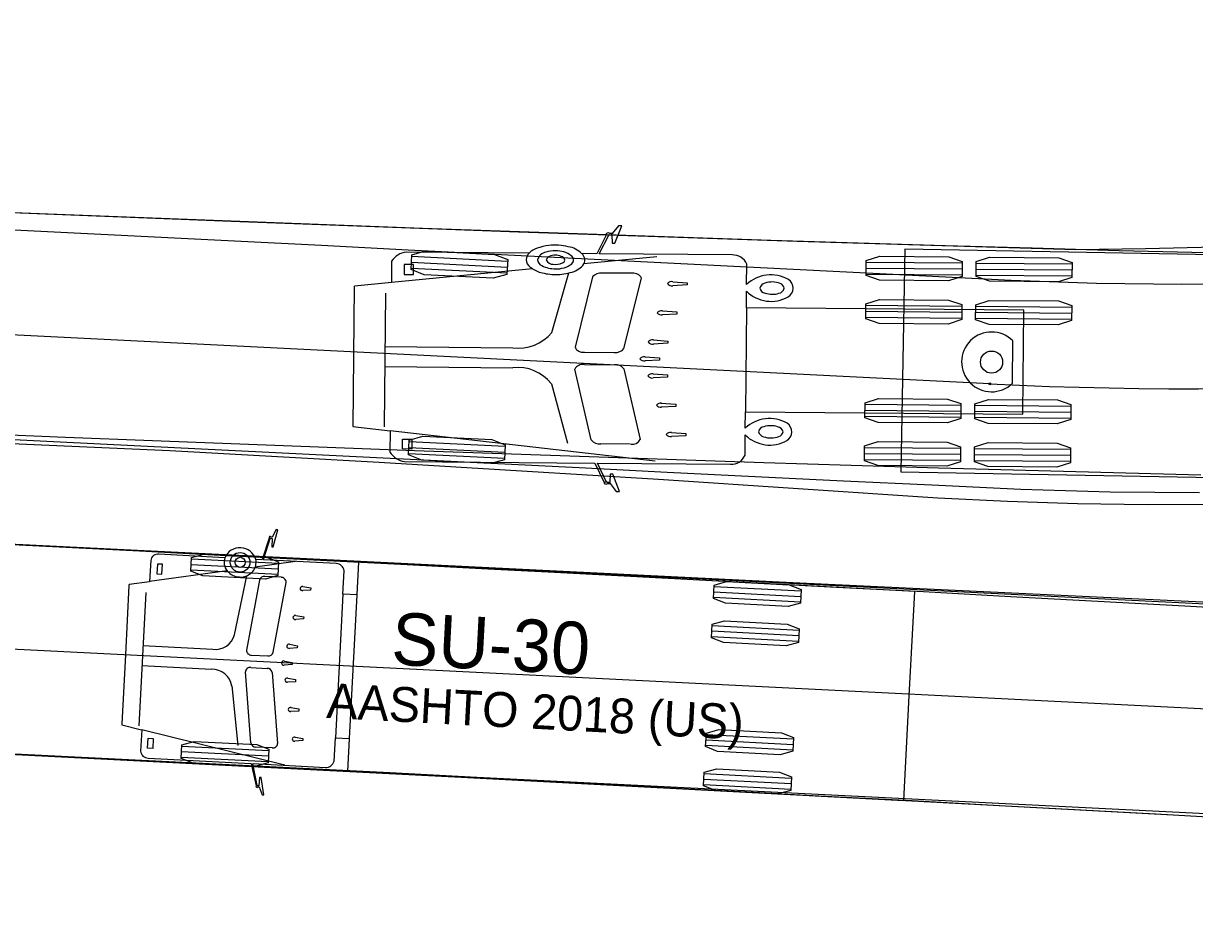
# Model space of a CAD drawing. Extents: x 260275 to 261282, y 610916 to 614143.
# Drawn here: x 260913.77 to 260958.53, y 612581.07 to 612614.79 of the extents above; entities that cross this region are included whole.
import ezdxf

# ---------------------------------------------------------------- set-up
doc = ezdxf.new("R2010")
doc.units = 0
doc.layers.add('TopoDOT_Transients', color=7, linetype='Continuous')

msp = doc.modelspace()

# ---------------------------------------------------------------- linework, layer by layer
at = {"layer": 'TopoDOT_Transients'}
for p, q in [((260950.706, 612601.011), (260777.483, 612609.681)), ((260936.261, 612606.737), (260936.278, 612606.757)), ((260936.262, 612606.711), (260936.261, 612606.737)), ((260933.106, 612606.005), (260928.405, 612606.046)), ((260928.323, 612605.571), (260928.32, 612605.192)), ((260928.679, 612605.568), (260928.323, 612605.571)), ((260928.605, 612605.661), (260932.267, 612605.477)), ((260928.616, 612605.89), (260932.278, 612605.706)), ((260928.676, 612605.189), (260928.679, 612605.568)), ((260937.981, 612605.862), (260935.19, 612605.593)), ((260941.411, 612604.807), (260941.417, 612605.582)), ((260945.985, 612605.663), (260949.651, 612605.631)), ((260950.185, 612605.626), (260953.851, 612605.594)), ((260933.234, 612605.405), (260927.837, 612604.886)), ((260928.32, 612605.192), (260928.676, 612605.189)), ((260928.593, 612605.432), (260932.255, 612605.248)), ((260933.967, 612602.978), (260934.623, 612605.249)), ((260935.522, 612605.097), (260934.854, 612602.409)), ((260937.024, 612605.236), (260935.893, 612605.246)), ((260945.981, 612605.205), (260949.647, 612605.173)), ((260945.983, 612605.434), (260949.649, 612605.402)), ((260950.181, 612605.168), (260953.847, 612605.136)), ((260950.183, 612605.397), (260953.849, 612605.365)), ((260926.409, 612604.748), (260926.363, 612599.378)), ((260936.725, 612602.362), (260937.393, 612605.051)), ((260939.137, 612604.793), (260938.587, 612604.762)), ((260938.588, 612604.916), (260939.138, 612604.876)), ((260939.138, 612604.876), (260939.137, 612604.793)), ((260927.608, 612604.472), (260927.564, 612599.367)), ((260938.193, 612603.803), (260938.742, 612603.762)), ((260938.742, 612603.762), (260938.742, 612603.679)), ((260941.403, 612603.919), (260941.368, 612599.945)), ((260945.968, 612603.784), (260949.635, 612603.752)), ((260945.97, 612604.013), (260949.637, 612603.981)), ((260950.168, 612603.747), (260953.835, 612603.715)), ((260950.17, 612603.976), (260953.837, 612603.944)), ((260938.742, 612603.679), (260938.192, 612603.648)), ((260945.966, 612603.555), (260949.633, 612603.523)), ((260950.166, 612603.518), (260953.833, 612603.486)), ((260927.591, 612602.435), (260932.482, 612602.393)), ((260938.398, 612602.565), (260937.848, 612602.534)), ((260937.849, 612602.688), (260938.398, 612602.648)), ((260938.398, 612602.648), (260938.398, 612602.565)), ((260951.574, 612601.035), (260951.588, 612602.651)), ((260935.222, 612602.224), (260936.353, 612602.214)), ((260937.535, 612602.043), (260938.084, 612602.002)), ((260938.084, 612602.002), (260938.083, 612601.92)), ((260927.584, 612601.67), (260932.475, 612601.627)), ((260935.467, 612598.87), (260934.846, 612601.57)), ((260935.218, 612601.748), (260936.349, 612601.738)), ((260936.718, 612601.583), (260937.339, 612598.884)), ((260938.083, 612601.92), (260937.534, 612601.889)), ((260938.386, 612601.269), (260937.836, 612601.238)), ((260937.838, 612601.392), (260938.387, 612601.351)), ((260938.387, 612601.351), (260938.386, 612601.269)), ((260933.949, 612601.016), (260934.563, 612598.746)), ((260938.711, 612600.149), (260938.136, 612600.117)), ((260938.137, 612600.271), (260938.712, 612600.231)), ((260938.712, 612600.231), (260938.711, 612600.149)), ((260945.937, 612600.23), (260949.604, 612600.198)), ((260950.137, 612600.193), (260953.804, 612600.161)), ((260945.933, 612599.771), (260949.6, 612599.739)), ((260945.935, 612600.001), (260949.602, 612599.969)), ((260950.133, 612599.735), (260953.8, 612599.703)), ((260950.135, 612599.964), (260953.802, 612599.932)), ((260937.913, 612598.062), (260927.788, 612599.215)), ((260928.261, 612598.522), (260928.265, 612598.901)), ((260928.265, 612598.901), (260928.621, 612598.898)), ((260928.516, 612598.807), (260932.179, 612598.625)), ((260928.621, 612598.898), (260928.617, 612598.519)), ((260939.087, 612599.028), (260938.537, 612598.997)), ((260938.538, 612599.151), (260939.087, 612599.111)), ((260939.087, 612599.111), (260939.087, 612599.028)), ((260941.354, 612598.282), (260941.36, 612599.058)), ((260928.617, 612598.519), (260928.261, 612598.522)), ((260928.505, 612598.578), (260932.167, 612598.396)), ((260936.967, 612598.705), (260935.836, 612598.715)), ((260945.923, 612598.58), (260949.59, 612598.548)), ((260950.123, 612598.543), (260953.789, 612598.511)), ((260928.494, 612598.349), (260932.156, 612598.167)), ((260945.919, 612598.122), (260949.586, 612598.09)), ((260945.921, 612598.351), (260949.588, 612598.319)), ((260950.119, 612598.085), (260953.785, 612598.053)), ((260950.121, 612598.314), (260953.787, 612598.282)), ((261025.504, 612585.252), (260776.884, 612597.696)), ((260936.18, 612597.243), (260936.178, 612597.217)), ((260936.178, 612597.217), (260936.195, 612597.197)), ((260921.472, 612594.365), (260918.953, 612594.498)), ((260918.892, 612594.125), (260918.872, 612593.747)), ((260919.085, 612594.115), (260918.892, 612594.125)), ((260919.066, 612593.737), (260919.085, 612594.115)), ((260920.175, 612593.903), (260923.504, 612593.737)), ((260920.185, 612594.111), (260923.514, 612593.945)), ((260920.196, 612594.32), (260923.525, 612594.153)), ((260924.17, 612594.223), (260922.636, 612594.01)), ((260921.561, 612593.862), (260918.594, 612593.451)), ((260918.872, 612593.747), (260919.066, 612593.737)), ((260921.844, 612591.423), (260922.31, 612593.677)), ((260922.793, 612593.508), (260922.3, 612590.836)), ((260923.619, 612593.617), (260923.003, 612593.649)), ((260918.449, 612593.042), (260918.181, 612587.944)), ((260923.318, 612590.752), (260923.811, 612593.425)), ((260924.75, 612593.132), (260924.448, 612593.112)), ((260924.456, 612593.266), (260924.754, 612593.215)), ((260924.754, 612593.215), (260924.75, 612593.132)), ((260940.159, 612593.064), (260943.487, 612592.888)), ((260940.17, 612593.272), (260943.498, 612593.096)), ((260925.983, 612592.972), (260925.694, 612587.488)), ((260926.514, 612592.944), (260926.225, 612587.46)), ((260940.148, 612592.856), (260943.477, 612592.68)), ((260924.188, 612592.162), (260924.485, 612592.11)), ((260924.485, 612592.11), (260924.481, 612592.028)), ((260924.481, 612592.028), (260924.179, 612592.008)), ((260940.091, 612591.774), (260943.42, 612591.599)), ((260940.069, 612591.358), (260943.398, 612591.182)), ((260940.08, 612591.566), (260943.409, 612591.391)), ((260918.342, 612591.008), (260921.007, 612590.868)), ((260924.24, 612590.922), (260923.939, 612590.902)), ((260923.947, 612591.056), (260924.244, 612591.004)), ((260924.244, 612591.004), (260924.24, 612590.922)), ((260922.493, 612590.644), (260923.108, 612590.612)), ((260923.745, 612590.417), (260924.042, 612590.366)), ((260924.042, 612590.366), (260924.038, 612590.283)), ((260918.302, 612590.243), (260920.967, 612590.103)), ((260922.466, 612587.289), (260922.256, 612589.998)), ((260922.468, 612590.169), (260923.083, 612590.137)), ((260923.277, 612589.975), (260923.487, 612587.266)), ((260924.038, 612590.283), (260923.736, 612590.263)), ((260921.741, 612589.463), (260921.967, 612587.184)), ((260924.172, 612589.627), (260923.87, 612589.607)), ((260923.879, 612589.761), (260924.176, 612589.709)), ((260924.176, 612589.709), (260924.172, 612589.627)), ((260923.988, 612588.636), (260924.299, 612588.584)), ((260924.299, 612588.584), (260924.295, 612588.502)), ((260924.295, 612588.502), (260923.98, 612588.482)), ((260923.76, 612586.434), (260918.296, 612587.788)), ((260939.872, 612587.613), (260943.2, 612587.438)), ((260918.521, 612587.086), (260918.541, 612587.464)), ((260918.541, 612587.464), (260918.735, 612587.454)), ((260918.735, 612587.454), (260918.715, 612587.076)), ((260919.821, 612587.163), (260923.15, 612586.996)), ((260924.446, 612587.375), (260924.145, 612587.355)), ((260924.153, 612587.509), (260924.451, 612587.458)), ((260924.451, 612587.458), (260924.446, 612587.375)), ((260939.85, 612587.197), (260943.178, 612587.022)), ((260939.861, 612587.405), (260943.189, 612587.23)), ((260918.715, 612587.076), (260918.521, 612587.086)), ((260919.8, 612586.747), (260923.129, 612586.58)), ((260919.81, 612586.955), (260923.14, 612586.788)), ((260923.275, 612587.095), (260922.659, 612587.127)), ((260939.782, 612585.907), (260943.111, 612585.732)), ((260939.793, 612586.115), (260943.121, 612585.94)), ((260939.771, 612585.699), (260943.1, 612585.524))]:
    msp.add_line(p, q, dxfattribs=at)
for points in [[(260911.385, 612607.632), (260922.039, 612607.21), (260932.691, 612606.819), (260943.342, 612606.462), (260953.993, 612606.15), (260956.658, 612606.184), (260959.324, 612606.244), (260961.99, 612606.332), (260964.656, 612606.454), (260967.323, 612606.613), (260969.991, 612606.814), (260972.66, 612607.058), (260975.329, 612607.346), (260977.999, 612607.674), (260980.67, 612608.042), (260983.343, 612608.449), (260986.018, 612608.892), (260988.694, 612609.369), (260991.374, 612609.879), (260994.059, 612610.418), (260996.748, 612610.983), (261002.487, 612612.256), (261003.848, 612612.757)], [(260958.984, 612606.013), (260955.656, 612606.101), (260952.328, 612606.193), (260949, 612606.289), (260945.672, 612606.389), (260942.344, 612606.494), (260939.016, 612606.602), (260935.687, 612606.715), (260932.359, 612606.83), (260929.03, 612606.95), (260925.701, 612607.072), (260922.372, 612607.198), (260919.043, 612607.326), (260915.714, 612607.457), (260912.384, 612607.591)], [(260961.3, 612604.839), (260958.04, 612604.805), (260954.781, 612604.844), (260951.526, 612604.955), (260948.258, 612605.122), (260944.976, 612605.291), (260941.686, 612605.459), (260938.39, 612605.627), (260935.089, 612605.794), (260931.782, 612605.96), (260928.472, 612606.127), (260925.159, 612606.293), (260921.843, 612606.46), (260918.524, 612606.626), (260915.204, 612606.792), (260911.882, 612606.959)], [(260936.18, 612606.711), (260936.262, 612606.711), (260936.275, 612606.391), (260936.378, 612606.39), (260936.642, 612607.049), (260936.522, 612607.05), (260936.278, 612606.757), (260936.191, 612606.757)], [(260936.057, 612606.718), (260935.682, 612605.982), (260935.108, 612605.987)], [(260940.863, 612605.937), (260935.781, 612605.981), (260936.143, 612606.7), (260936.144, 612606.7)], [(260995.384, 612605.258), (260995.384, 612605.281), (260947.463, 612606.153), (260947.386, 612601.903), (260947.308, 612597.654), (260995.23, 612596.782), (260995.23, 612596.804)], [(260927.844, 612605.7), (260927.837, 612604.886), (260926.421, 612604.749)], [(260926.409, 612604.748), (260926.363, 612599.378), (260927.788, 612599.215), (260927.781, 612598.401)], [(260941.363, 612599.315), (260941.368, 612599.945), (260951.968, 612599.853), (260952.002, 612603.826), (260941.403, 612603.919), (260941.408, 612604.549)], [(261003.728, 612596.585), (260998.439, 612596.713), (260972.791, 612597.178), (260970.113, 612596.922), (260967.436, 612596.717), (260964.759, 612596.562), (260962.082, 612596.455), (260959.407, 612596.397), (260956.732, 612596.387), (260954.059, 612596.425), (260951.386, 612596.511), (260948.716, 612596.644), (260938.041, 612597.354), (260927.368, 612598.004), (260919.365, 612598.455), (260908.692, 612598.918)], [(260958.718, 612596.842), (260955.304, 612596.87), (260951.89, 612596.973), (260948.494, 612597.133), (260945.113, 612597.298), (260941.739, 612597.463), (260938.372, 612597.629), (260935.011, 612597.796), (260931.655, 612597.963), (260928.302, 612598.13), (260924.953, 612598.297), (260921.607, 612598.464), (260918.263, 612598.631), (260914.921, 612598.798), (260911.58, 612598.965)], [(260958.767, 612597.516), (260955.428, 612597.604), (260952.089, 612597.696), (260948.75, 612597.793), (260945.411, 612597.893), (260942.073, 612597.998), (260938.734, 612598.107), (260935.396, 612598.22), (260932.059, 612598.336), (260928.722, 612598.455), (260925.385, 612598.578), (260922.048, 612598.704), (260918.712, 612598.833), (260915.376, 612598.964), (260912.04, 612599.098)], [(260928.335, 612598.046), (260935.612, 612597.982), (260935.974, 612597.24)], [(260936.061, 612597.256), (260936.061, 612597.256), (260935.711, 612597.981), (260940.793, 612597.937)], [(260936.107, 612597.198), (260936.195, 612597.197), (260936.433, 612596.9), (260936.553, 612596.899), (260936.301, 612597.563), (260936.198, 612597.563), (260936.18, 612597.243), (260936.098, 612597.245)], [(260900.569, 612595.515), (260943.182, 612593.414), (260964.509, 612592.414), (260975.188, 612591.95), (260985.89, 612591.53), (260991.256, 612591.343), (260996.637, 612591.176), (261002.039, 612591.033), (261007.472, 612590.914)], [(260923.23, 612595.107), (260923.274, 612595.106), (260923.274, 612595.105), (260923.266, 612594.788), (260923.266, 612594.785), (260923.322, 612594.782), (260923.323, 612594.785), (260923.497, 612595.433), (260923.497, 612595.436), (260923.432, 612595.439), (260923.285, 612595.151), (260923.285, 612595.151), (260923.237, 612595.153)], [(260961.528, 612592.459), (260958.19, 612592.626), (260954.854, 612592.793), (260951.52, 612592.96), (260948.186, 612593.127), (260944.853, 612593.294), (260941.521, 612593.461), (260938.189, 612593.627), (260934.858, 612593.794), (260931.528, 612593.961), (260928.197, 612594.128), (260924.867, 612594.294), (260921.538, 612594.461), (260918.208, 612594.628), (260914.879, 612594.794), (260911.55, 612594.961)], [(260961.494, 612592.322), (260958.163, 612592.51), (260954.832, 612592.695), (260951.502, 612592.877), (260948.172, 612593.056), (260944.842, 612593.234), (260941.512, 612593.41), (260938.183, 612593.584), (260934.853, 612593.757), (260931.524, 612593.93), (260928.195, 612594.101), (260924.867, 612594.272), (260921.538, 612594.442), (260918.209, 612594.611), (260914.881, 612594.78), (260911.552, 612594.949)], [(260923.162, 612595.116), (260923.162, 612595.116), (260922.893, 612594.297), (260922.88, 612594.291), (260922.653, 612594.303)], [(260925.729, 612594.141), (260922.958, 612594.287), (260922.946, 612594.292), (260923.209, 612595.097), (260923.209, 612595.097)], [(260918.637, 612594.261), (260918.594, 612593.454), (260918.589, 612593.45), (260917.811, 612593.342), (260917.807, 612593.3), (260917.668, 612590.66), (260917.529, 612588.02), (260917.529, 612587.978), (260918.291, 612587.789), (260918.296, 612587.784), (260918.253, 612586.978)], [(260925.647, 612586.59), (260925.694, 612587.484), (260925.698, 612587.487), (260926.224, 612587.46), (260926.224, 612587.449), (260926.159, 612586.207), (260947.416, 612585.088), (260947.626, 612589.082), (260947.837, 612593.077), (260926.58, 612594.196), (260926.514, 612592.955), (260926.513, 612592.944), (260925.987, 612592.972), (260925.983, 612592.975), (260926.03, 612593.87)], [(261004.659, 612581.071), (260999.422, 612581.614), (260994.161, 612582.095), (260988.884, 612582.526), (260983.594, 612582.919), (260978.296, 612583.283), (260967.681, 612583.949), (260957.051, 612584.56), (260935.769, 612585.699), (260893.177, 612587.866)], [(260961.01, 612584.476), (260957.69, 612584.642), (260954.37, 612584.808), (260951.048, 612584.974), (260947.725, 612585.14), (260944.401, 612585.307), (260941.077, 612585.473), (260937.752, 612585.639), (260934.427, 612585.806), (260931.101, 612585.972), (260927.775, 612586.139), (260924.448, 612586.305), (260921.121, 612586.472), (260917.794, 612586.638), (260914.467, 612586.805), (260911.14, 612586.971)], [(260961.039, 612584.335), (260957.716, 612584.523), (260954.392, 612584.707), (260951.068, 612584.888), (260947.743, 612585.068), (260944.418, 612585.245), (260941.092, 612585.421), (260937.765, 612585.595), (260934.439, 612585.768), (260931.112, 612585.94), (260927.785, 612586.112), (260924.458, 612586.282), (260921.13, 612586.452), (260917.803, 612586.622), (260914.475, 612586.791), (260911.147, 612586.959)], [(260918.542, 612586.709), (260922.47, 612586.502), (260922.482, 612586.494), (260922.664, 612585.652), (260922.664, 612585.651)], [(260922.712, 612585.666), (260922.712, 612585.666), (260922.536, 612586.494), (260922.548, 612586.498), (260925.318, 612586.352)], [(260922.735, 612585.607), (260922.782, 612585.604), (260922.782, 612585.604), (260922.898, 612585.302), (260922.963, 612585.299), (260922.963, 612585.301), (260922.858, 612585.964), (260922.857, 612585.967), (260922.802, 612585.97), (260922.801, 612585.967), (260922.776, 612585.651), (260922.776, 612585.65), (260922.732, 612585.653)]]:
    msp.add_lwpolyline(points, dxfattribs=at)
for points in [[(260928.59, 612605.376), (260928.619, 612605.947), (260929.141, 612606.093), (260931.777, 612605.961), (260932.281, 612605.763), (260932.252, 612605.191), (260931.731, 612605.045), (260929.094, 612605.178)], [(260945.98, 612605.148), (260945.985, 612605.72), (260946.5, 612605.888), (260949.14, 612605.865), (260949.652, 612605.688), (260949.647, 612605.116), (260949.132, 612604.948), (260946.492, 612604.971)], [(260950.18, 612605.111), (260950.185, 612605.683), (260950.7, 612605.851), (260953.34, 612605.828), (260953.852, 612605.651), (260953.847, 612605.079), (260953.332, 612604.911), (260950.692, 612604.934)], [(260945.966, 612603.498), (260945.971, 612604.07), (260946.486, 612604.238), (260949.126, 612604.215), (260949.637, 612604.038), (260949.632, 612603.466), (260949.118, 612603.298), (260946.478, 612603.321)], [(260950.166, 612603.461), (260950.171, 612604.033), (260950.686, 612604.201), (260953.326, 612604.178), (260953.837, 612604.001), (260953.832, 612603.429), (260953.318, 612603.261), (260950.678, 612603.284)], [(260945.933, 612599.715), (260945.938, 612600.287), (260946.453, 612600.454), (260949.093, 612600.431), (260949.604, 612600.255), (260949.599, 612599.683), (260949.085, 612599.515), (260946.445, 612599.538)], [(260950.133, 612599.678), (260950.138, 612600.25), (260950.653, 612600.418), (260953.292, 612600.395), (260953.804, 612600.218), (260953.799, 612599.646), (260953.284, 612599.478), (260950.645, 612599.501)], [(260928.491, 612598.293), (260928.519, 612598.864), (260929.041, 612599.011), (260931.677, 612598.879), (260932.181, 612598.682), (260932.153, 612598.11), (260931.632, 612597.964), (260928.995, 612598.095)], [(260945.919, 612598.065), (260945.924, 612598.637), (260946.438, 612598.805), (260949.078, 612598.781), (260949.59, 612598.605), (260949.585, 612598.033), (260949.07, 612597.865), (260946.43, 612597.888)], [(260950.118, 612598.028), (260950.123, 612598.6), (260950.638, 612598.768), (260953.278, 612598.745), (260953.79, 612598.568), (260953.785, 612597.996), (260953.27, 612597.828), (260950.63, 612597.851)], [(260920.172, 612593.852), (260920.198, 612594.371), (260920.672, 612594.504), (260923.069, 612594.384), (260923.527, 612594.205), (260923.501, 612593.685), (260923.027, 612593.552), (260920.63, 612593.672)], [(260940.145, 612592.804), (260940.172, 612593.323), (260940.647, 612593.455), (260943.043, 612593.329), (260943.501, 612593.148), (260943.474, 612592.629), (260943, 612592.497), (260940.603, 612592.623)], [(260940.066, 612591.306), (260940.094, 612591.825), (260940.568, 612591.957), (260942.964, 612591.831), (260943.422, 612591.65), (260943.395, 612591.131), (260942.921, 612590.999), (260940.524, 612591.125)], [(260939.847, 612587.145), (260939.874, 612587.665), (260940.349, 612587.796), (260942.745, 612587.67), (260943.203, 612587.489), (260943.176, 612586.97), (260942.701, 612586.838), (260940.305, 612586.964)], [(260919.797, 612586.695), (260919.823, 612587.214), (260920.297, 612587.347), (260922.694, 612587.227), (260923.153, 612587.048), (260923.127, 612586.528), (260922.653, 612586.395), (260920.256, 612586.515)], [(260939.768, 612585.647), (260939.795, 612586.167), (260940.27, 612586.299), (260942.666, 612586.172), (260943.124, 612585.991), (260943.097, 612585.472), (260942.623, 612585.34), (260940.226, 612585.466)]]:
    msp.add_lwpolyline(points, close=True, dxfattribs=at)
for centre, radius in [((260950.773, 612601.842), 0.424), ((260950.706, 612601.011), 0.0417), ((260950.706, 612601.011), 0.0417), ((260922.054, 612594.189), 0.374), ((260922.054, 612594.189), 0.193)]:
    msp.add_circle(centre, radius, dxfattribs=at)
for centre, radius, start, end in [((260958.205, 612750.824), 150, 267.13462, 294.9182), ((260936.07, 612606.739), 0.0244, 125.3178, 238.6321), ((260936.122, 612606.65), 0.127, 57.3952, 121.6043), ((260936.131, 612606.81), 0.11, 276.4439, 296.5522), ((260928.502, 612605.26), 0.792, 97.0332, 146.1886), ((260933.315, 612605.752), 0.328, 129.5881, 178.4924), ((260933.625, 612605.508), 0.719, 108.0301, 136.2871), ((260934.025, 612604.576), 1.731, 95.8848, 111.0826), ((260933.814, 612605.641), 0.407, 100.7304, 163.5348), ((260934.093, 612604.859), 1.234, 89.1294, 106.7116), ((260934.091, 612604.108), 2.204, 76.6988, 96.334), ((260934.161, 612605.182), 0.913, 52.8094, 93.0696), ((260934.448, 612605.341), 0.924, 44.3968, 80.675), ((260934.93, 612605.745), 0.301, 329.731, 53.6293), ((260933.366, 612605.779), 0.38, 182.8301, 233.3536), ((260933.69, 612605.778), 0.268, 184.5724, 248.25), ((260934.093, 612606.506), 1.098, 242.7655, 270.6581), ((260933.965, 612605.687), 0.22, 100.5096, 162.2079), ((260934.008, 612605.849), 0.27, 200.6487, 273.3925), ((260934.1, 612605.296), 0.631, 63.308, 106.1085), ((260934.112, 612606.19), 0.617, 261.7873, 294.9781), ((260934.164, 612606.32), 0.914, 266.3342, 308.3921), ((260934.342, 612605.747), 0.12, 284.4758, 69.9539), ((260934.596, 612605.748), 0.199, 313.303, 53.9423), ((260934.539, 612606.056), 0.799, 285.2992, 324.5668), ((260940.888, 612605.366), 0.571, 22.1928, 92.5843), ((260933.816, 612606.308), 1.074, 230.9563, 255.2252), ((260934.111, 612607.239), 2.049, 253.8808, 269.8061), ((260934.134, 612607.201), 2.012, 269.1411, 287.824), ((260935.837, 612604.846), 0.403, 82.0421, 141.5), ((260937.092, 612604.906), 0.334, 25.7646, 98.3626), ((260942.335, 612603.831), 1.344, 59.9095, 133.4643), ((260938.545, 612604.729), 0.192, 76.9495, 144.424), ((260938.547, 612604.95), 0.192, 214.5481, 282.0773), ((260942.19, 612604.583), 0.29, 105.6954, 161.8555), ((260942.157, 612604.722), 0.247, 191.217, 261.0961), ((260942.376, 612604.045), 0.86, 67.9644, 107.9338), ((260942.6, 612604.73), 0.262, 279.1826, 345.7078), ((260942.629, 612604.625), 0.228, 10.3026, 72.1974), ((260942.811, 612604.666), 0.383, 299.9705, 59.029), ((260942.349, 612605.508), 1.344, 225.5352, 299.09), ((260942.39, 612605.314), 0.879, 252.0366, 286.6318), ((260938.15, 612603.615), 0.192, 76.9495, 144.424), ((260938.152, 612603.836), 0.192, 214.5481, 282.0773), ((260932.702, 612604.009), 1.631, 262.2332, 320.8239), ((260950.773, 612601.85), 1.143, 44.4997, 314.4997), ((260935.156, 612602.562), 0.342, 207.9714, 277.8979), ((260937.806, 612602.501), 0.192, 76.9495, 144.424), ((260937.808, 612602.722), 0.192, 214.5481, 282.0773), ((260936.413, 612602.608), 0.397, 263.5756, 321.7386), ((260937.491, 612601.856), 0.192, 76.9495, 144.424), ((260937.493, 612602.077), 0.192, 214.5754, 282.05), ((260932.667, 612600.008), 1.631, 38.1756, 96.7663), ((260935.145, 612601.411), 0.342, 81.1015, 151.028), ((260936.402, 612601.343), 0.397, 37.2609, 95.4239), ((260937.794, 612601.205), 0.192, 76.9221, 144.4514), ((260937.796, 612601.426), 0.192, 214.5754, 282.05), ((260938.119, 612600.085), 0.192, 76.9221, 144.4514), ((260938.121, 612600.306), 0.192, 214.5754, 282.05), ((260942.287, 612598.34), 1.344, 59.9095, 133.4643), ((260942.108, 612599.13), 0.247, 97.9033, 167.7824), ((260942.331, 612598.533), 0.879, 72.3676, 106.9629), ((260942.551, 612599.113), 0.262, 13.2917, 79.8169), ((260942.755, 612599.174), 0.387, 300.9953, 58.0042), ((260935.787, 612599.115), 0.403, 217.4994, 276.9574), ((260937.041, 612599.034), 0.334, 260.6369, 333.2349), ((260938.495, 612598.964), 0.192, 76.9221, 144.4514), ((260938.497, 612599.185), 0.192, 214.5754, 282.05), ((260942.301, 612600.016), 1.344, 225.5352, 299.09), ((260942.144, 612599.267), 0.29, 197.144, 253.304), ((260942.339, 612599.803), 0.86, 251.0657, 291.0351), ((260942.582, 612599.218), 0.228, 286.802, 348.6969), ((260928.446, 612598.83), 0.792, 212.8108, 261.9663), ((260940.829, 612598.507), 0.571, 266.4151, 336.8067), ((260935.987, 612597.219), 0.0244, 120.3673, 233.6817), ((260936.041, 612597.307), 0.127, 237.3952, 301.6043), ((260936.047, 612597.147), 0.11, 62.4472, 82.5556), ((260923.2, 612595.134), 0.0418, 27.478, 204.493), ((260923.201, 612595.14), 0.0434, 280.8984, 311.5712), ((260918.915, 612594.219), 0.282, 82.357, 171.4365), ((260921.968, 612594.193), 0.526, 160.93, 219.176), ((260922.051, 612594.122), 0.628, 16.7382, 157.2299), ((260922.141, 612594.185), 0.524, 319.2439, 13.044), ((260925.712, 612593.819), 0.323, 9.1365, 86.9849), ((260922.05, 612594.258), 0.629, 219.0305, 267.7198), ((260922.065, 612594.258), 0.63, 266.3397, 318.7425), ((260922.979, 612593.458), 0.193, 82.928, 164.8425), ((260923.627, 612593.432), 0.184, 357.5774, 92.4487), ((260924.433, 612593.178), 0.091, 75.3014, 169.4653), ((260924.435, 612593.202), 0.0909, 184.4688, 278.704), ((260924.165, 612592.074), 0.091, 75.3014, 169.4653), ((260924.166, 612592.098), 0.0909, 184.4688, 278.704), ((260921.101, 612591.635), 0.773, 263.0102, 344.0944), ((260922.485, 612590.828), 0.184, 177.583, 272.4431), ((260923.132, 612590.803), 0.193, 262.923, 344.8474), ((260923.924, 612590.968), 0.091, 75.3014, 169.4653), ((260923.925, 612590.992), 0.0909, 184.4688, 278.704), ((260923.722, 612590.329), 0.091, 75.3014, 169.4653), ((260923.723, 612590.353), 0.091, 184.5044, 278.6683), ((260920.979, 612589.33), 0.773, 9.8753, 90.9595), ((260922.44, 612589.987), 0.184, 81.5266, 176.3867), ((260923.087, 612589.944), 0.193, 9.1224, 91.0467), ((260923.855, 612589.673), 0.0909, 75.2658, 169.501), ((260923.857, 612589.697), 0.091, 184.5044, 278.6683), ((260923.979, 612588.548), 0.0909, 75.2658, 169.501), ((260923.98, 612588.572), 0.091, 184.5044, 278.6683), ((260922.656, 612587.32), 0.193, 189.1273, 271.0418), ((260923.303, 612587.277), 0.184, 261.521, 356.3923), ((260924.13, 612587.421), 0.0909, 75.2658, 169.501), ((260924.131, 612587.445), 0.091, 184.5044, 278.6683), ((260918.535, 612586.99), 0.282, 182.5333, 271.6127), ((260925.335, 612586.674), 0.323, 266.9849, 344.8333), ((260922.7, 612585.63), 0.0418, 149.4768, 326.4917), ((260922.7, 612585.624), 0.0434, 42.3986, 73.0714)]:
    msp.add_arc(centre, radius, start, end, dxfattribs=at)
for centre, major_axis, start_param, end_param in [((260936.123, 612606.738), (0.0782, -0.0007), 3.71124, 4.981984), ((260936.123, 612606.738), (-0.0782, 0.0007), 2.398717, 3.668019), ((260936.04, 612597.219), (-0.0782, 0.0007), 4.442794, 5.713538), ((260936.04, 612597.219), (0.0782, -0.0007), 5.756759, 7.026061)]:
    msp.add_ellipse(centre, major_axis=major_axis, ratio=0.5, start_param=start_param, end_param=end_param, dxfattribs=at)

# ---------------------------------------------------------------- texts
for s, height, p in [('SU-30', 2, (260927.805, 612590.286)), ('AASHTO 2018 (US)', 1.33333, (260925.337, 612588.247))]:
    msp.add_text(s, height=height, rotation=356.9849, dxfattribs=at).set_placement(p)

doc.saveas('drawing.dxf')
